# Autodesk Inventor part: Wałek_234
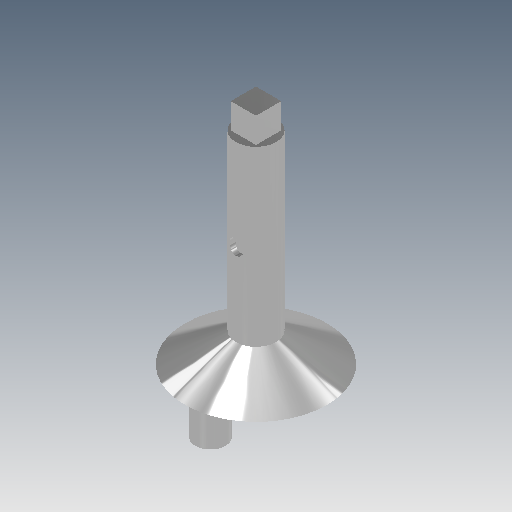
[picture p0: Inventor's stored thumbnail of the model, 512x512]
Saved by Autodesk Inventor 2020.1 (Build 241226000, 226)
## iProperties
Created: 2005-09
Part Number: Wałek_234
Document SubType Name: Modeling
Designer: F.Stasiak
Density: 1 g/cm^3
Material: Ogólny
Appearance: Chrom — polerowany
Manager: www.cadconsulting.pl
Company: Fabian Stasiak CAD Consulting
Author: F.Stasiak
Subject: Zbiór ćwiczeń. Autodesk Inventor 2020. Kurs podstawowy
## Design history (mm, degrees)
feature "Baza1"
node "Oś konstrukcyjna1"
node "Oś konstrukcyjna2"
node "Płaszczyzna konstrukcyjna1"
node "Bryła1"
node "Korpusy bryłowe"
node "Korpusy powierzchniowe"
